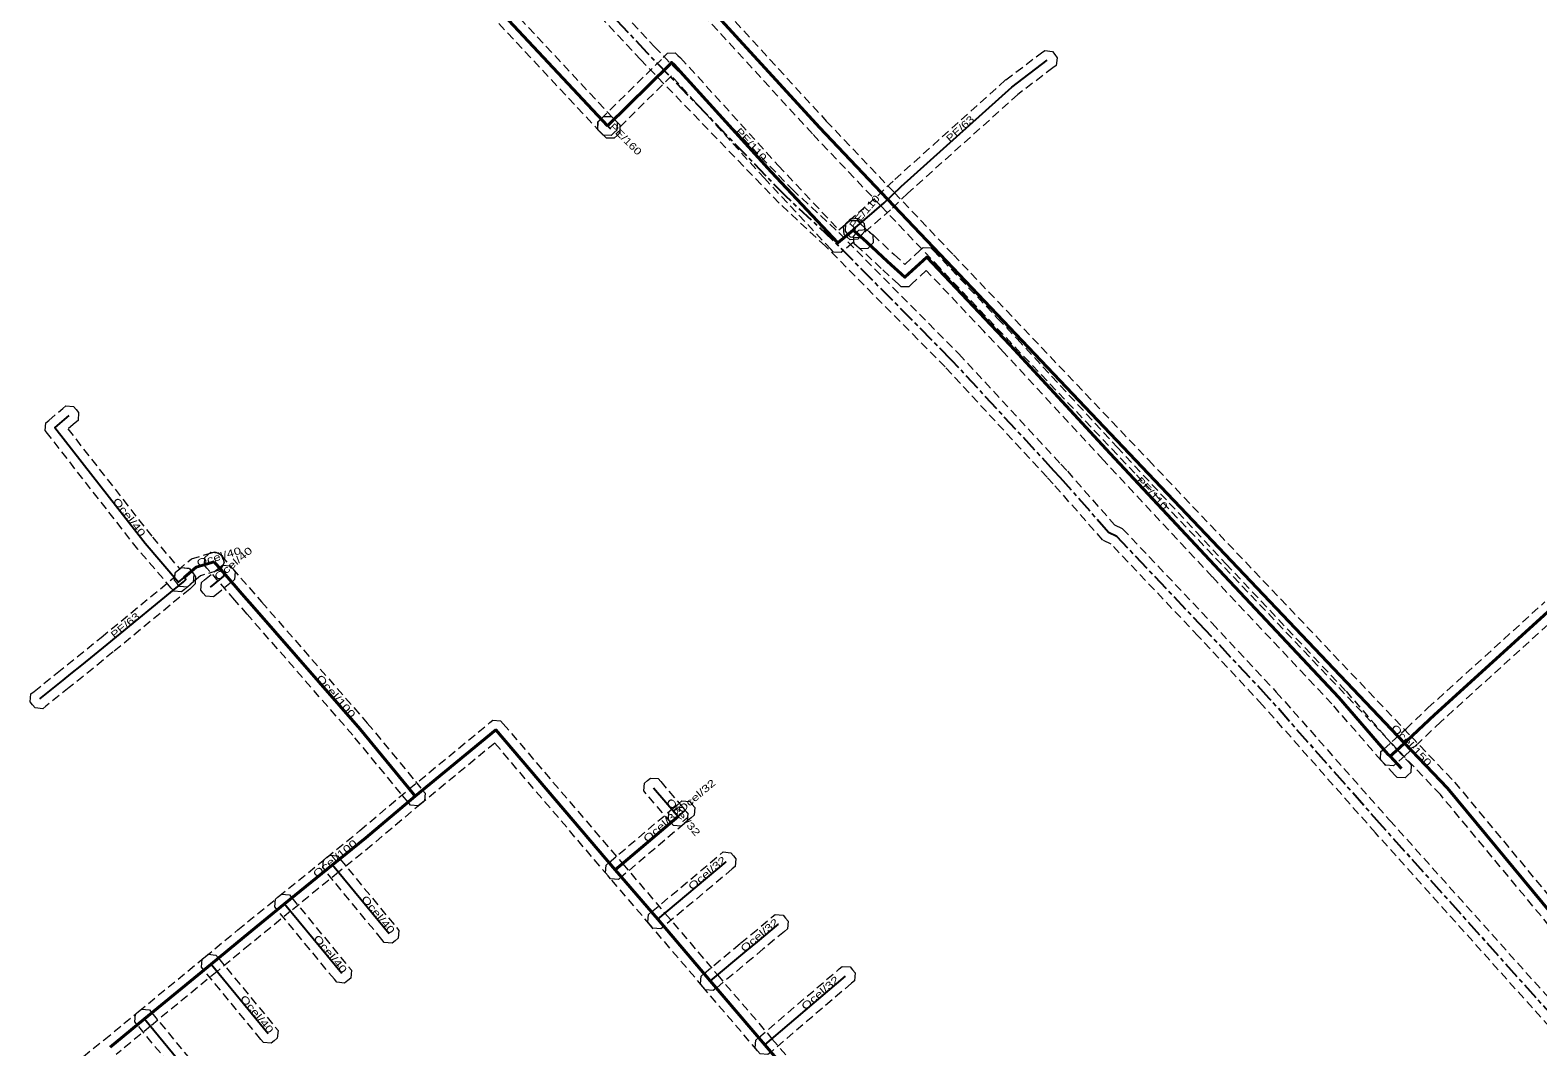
# Model space of a CAD drawing. Extents: x -588392 to -586332, y -1208963 to -1206334.
# Drawn here: x -588286.3 to -588126.9, y -1206548.1 to -1206440.6 of the extents above; entities that cross this region are included whole.
import ezdxf

# ---------------------------------------------------------------- set-up
doc = ezdxf.new("R2010")
doc.units = 0
doc.header["$LTSCALE"] = 0.3
doc.linetypes.add('LONG_DASH_SHORT_DASH', pattern=[9.9, 6, -1.2, 1.5, -1.2])
doc.linetypes.add('MEDIUM_DASHED', pattern=[4.5, 3, -1.5])
for name, color, linetype, lineweight in [('1', 7, 'MEDIUM_DASHED', 13), ('14', 7, 'Continuous', 25), ('24', 7, 'Continuous', 25), ('55', 7, 'LONG_DASH_SHORT_DASH', 25), ('7', 7, 'MEDIUM_DASHED', 13)]:
    doc.layers.add(name, color=color, linetype=linetype, lineweight=lineweight)
doc.layers.add('20', color=7, linetype='Continuous')
doc.layers.add('30', color=7, linetype='Continuous')

msp = doc.modelspace()

# ---------------------------------------------------------------- linework, layer by layer
at = {"layer": '1'}
for points in [[(-588105.041, -1206560.272), (-588137.218, -1206521.444), (-588141.774, -1206516.649), (-588169.516, -1206487.445), (-588190.167, -1206465.706), (-588196.423, -1206459.121), (-588203.622, -1206451.542), (-588247.155, -1206403.949), (-588247.425, -1206403.435), (-588247.618, -1206403.068), (-588247.372, -1206402.277), (-588247.005, -1206402.085), (-588246.638, -1206401.892), (-588245.847, -1206402.138), (-588245.655, -1206402.505), (-588245.505, -1206402.791), (-588202.158, -1206450.178), (-588194.973, -1206457.743), (-588188.717, -1206464.328), (-588168.066, -1206486.067), (-588140.324, -1206515.271), (-588135.722, -1206520.116), (-588103.501, -1206558.996)], [(-588242.864, -1206430.433), (-588224.569, -1206450.007), (-588224.287, -1206450.31), (-588224.315, -1206451.138), (-588224.617, -1206451.421), (-588224.92, -1206451.703), (-588225.748, -1206451.675), (-588226.031, -1206451.373), (-588244.316, -1206431.807)], [(-588124.832, -1206502.544), (-588137.17, -1206513.743), (-588139.475, -1206515.929), (-588140.957, -1206517.31), (-588141.866, -1206518.117), (-588142.175, -1206518.392), (-588143.002, -1206518.344), (-588143.277, -1206518.034), (-588143.552, -1206517.725), (-588143.504, -1206516.898), (-588143.194, -1206516.623), (-588142.303, -1206515.83), (-588140.845, -1206514.471), (-588138.53, -1206512.277), (-588126.168, -1206501.056)], [(-588282.82, -1206550.873), (-588278.513, -1206547.385), (-588274.885, -1206544.398), (-588267.845, -1206538.608), (-588264.394, -1206535.767), (-588260.072, -1206532.235), (-588254.991, -1206528.105), (-588251.478, -1206525.24), (-588246.26, -1206520.841), (-588237.725, -1206513.827), (-588237.409, -1206513.568), (-588236.594, -1206513.64), (-588236.329, -1206513.951), (-588223.71, -1206528.741), (-588219.229, -1206533.981), (-588213.679, -1206540.501), (-588207.9, -1206547.27), (-588200.519, -1206555.901)], [(-588209.42, -1206548.57), (-588215.201, -1206541.799), (-588220.751, -1206535.279), (-588225.23, -1206530.039), (-588237.214, -1206515.996), (-588244.98, -1206522.379), (-588250.202, -1206526.78), (-588253.729, -1206529.655), (-588258.808, -1206533.785), (-588263.126, -1206537.313), (-588266.575, -1206540.152), (-588273.615, -1206545.942), (-588277.247, -1206548.935)]]:
    msp.add_lwpolyline(points, dxfattribs=at)
for points in [[(-588208.705, -1206456.238), (-588218.522, -1206445.4), (-588224.597, -1206451.401), (-588224.892, -1206451.692), (-588225.72, -1206451.688), (-588226.011, -1206451.393), (-588226.302, -1206451.098), (-588226.298, -1206450.27), (-588226.003, -1206449.979), (-588219.415, -1206443.471), (-588219.217, -1206443.273), (-588218.938, -1206442.994), (-588218.149, -1206442.967), (-588217.851, -1206443.227), (-588217.568, -1206443.476), (-588207.235, -1206454.882), (-588200.846, -1206461.697), (-588199.941, -1206460.942), (-588199.653, -1206460.702), (-588198.903, -1206460.718), (-588198.626, -1206460.971), (-588197.559, -1206461.945), (-588197.253, -1206462.225), (-588197.215, -1206463.052), (-588197.494, -1206463.358), (-588197.774, -1206463.664), (-588198.601, -1206463.702), (-588198.907, -1206463.423), (-588199.33, -1206463.037), (-588200.289, -1206463.838), (-588200.594, -1206464.093), (-588201.388, -1206464.044), (-588201.66, -1206463.754)], [(-588200.078, -1206461.005), (-588199.765, -1206460.734), (-588196.714, -1206458.091), (-588194.911, -1206456.357), (-588183.177, -1206445.818), (-588179.394, -1206442.953), (-588179.064, -1206442.703), (-588178.243, -1206442.816), (-588177.993, -1206443.146), (-588177.743, -1206443.476), (-588177.856, -1206444.297), (-588178.186, -1206444.547), (-588181.903, -1206447.362), (-588193.549, -1206457.823), (-588195.366, -1206459.569), (-588198.455, -1206462.246), (-588198.768, -1206462.517), (-588199.595, -1206462.458), (-588199.866, -1206462.145), (-588200.137, -1206461.832)], [(-588224.886, -1206449.69), (-588224.593, -1206449.983), (-588224.283, -1206450.293), (-588223.99, -1206450.586), (-588223.99, -1206451.414), (-588224.283, -1206451.707), (-588224.576, -1206452), (-588225.404, -1206452), (-588225.697, -1206451.707), (-588226.007, -1206451.397), (-588226.3, -1206451.104), (-588226.3, -1206450.276), (-588226.007, -1206449.983), (-588225.714, -1206449.69)], [(-588198.083, -1206461.83), (-588198.353, -1206462.144), (-588198.543, -1206462.364), (-588198.814, -1206462.677), (-588199.64, -1206462.737), (-588199.954, -1206462.467), (-588200.267, -1206462.196), (-588200.327, -1206461.37), (-588200.057, -1206461.056), (-588199.867, -1206460.836), (-588199.596, -1206460.523), (-588198.77, -1206460.463), (-588198.456, -1206460.733), (-588198.143, -1206461.004)], [(-588197.908, -1206461.652), (-588197.59, -1206461.918), (-588197.217, -1206462.231), (-588194.992, -1206464.305), (-588193.847, -1206465.35), (-588192.221, -1206463.838), (-588191.919, -1206463.557), (-588191.096, -1206463.584), (-588190.813, -1206463.883), (-588184.044, -1206471.053), (-588181.99, -1206473.216), (-588171.407, -1206484.67), (-588159.89, -1206497.026), (-588147.198, -1206510.509), (-588142.035, -1206516.46), (-588141.816, -1206516.669), (-588140.595, -1206517.992), (-588140.314, -1206518.296), (-588140.348, -1206519.124), (-588140.652, -1206519.405), (-588140.956, -1206519.686), (-588141.784, -1206519.652), (-588142.065, -1206519.348), (-588143.244, -1206518.071), (-588143.485, -1206517.84), (-588148.682, -1206511.851), (-588161.35, -1206498.394), (-588172.873, -1206486.03), (-588183.45, -1206474.584), (-588185.496, -1206472.427), (-588191.586, -1206465.978), (-588193.159, -1206467.442), (-588193.445, -1206467.708), (-588194.225, -1206467.712), (-588194.514, -1206467.449), (-588196.348, -1206465.775), (-588198.543, -1206463.729), (-588198.876, -1206463.45), (-588199.193, -1206463.184), (-588199.265, -1206462.359), (-588198.999, -1206462.041), (-588198.733, -1206461.724)], [(-588273.415, -1206494.207), (-588270.548, -1206497.562), (-588270.392, -1206497.43), (-588269.566, -1206497.496), (-588269.298, -1206497.812), (-588269.03, -1206498.128), (-588269.096, -1206498.954), (-588269.412, -1206499.222), (-588270.012, -1206499.732), (-588270.327, -1206500), (-588271.151, -1206499.934), (-588271.42, -1206499.62), (-588274.965, -1206495.473), (-588284.528, -1206483.225), (-588284.776, -1206482.908), (-588284.693, -1206482.106), (-588284.386, -1206481.846), (-588282.896, -1206480.586), (-588282.58, -1206480.319), (-588281.754, -1206480.388), (-588281.486, -1206480.704), (-588281.219, -1206481.02), (-588281.288, -1206481.846), (-588281.604, -1206482.114), (-588282.36, -1206482.753)], [(-588271.025, -1206497.97), (-588270.71, -1206497.7), (-588269.299, -1206496.492), (-588267.186, -1206495.862), (-588266.789, -1206495.744), (-588266.06, -1206496.137), (-588265.942, -1206496.534), (-588265.824, -1206496.931), (-588266.217, -1206497.66), (-588266.614, -1206497.778), (-588268.321, -1206498.288), (-588269.41, -1206499.22), (-588269.724, -1206499.489), (-588270.55, -1206499.425), (-588270.82, -1206499.11), (-588271.089, -1206498.796)], [(-588266.421, -1206495.85), (-588266.148, -1206496.161), (-588264.947, -1206497.532), (-588263.196, -1206499.543), (-588261.877, -1206501.052), (-588250.697, -1206513.873), (-588245.598, -1206520.064), (-588244.848, -1206520.974), (-588244.585, -1206521.294), (-588244.664, -1206522.119), (-588244.984, -1206522.382), (-588245.304, -1206522.645), (-588246.129, -1206522.566), (-588246.392, -1206522.246), (-588247.142, -1206521.336), (-588252.223, -1206515.167), (-588263.383, -1206502.368), (-588264.704, -1206500.857), (-588266.453, -1206498.848), (-588267.652, -1206497.479), (-588267.925, -1206497.168), (-588267.87, -1206496.341), (-588267.559, -1206496.068), (-588267.248, -1206495.795)], [(-588278.822, -1206504.805), (-588271.064, -1206498.416), (-588270.991, -1206497.909), (-588270.66, -1206497.66), (-588270.329, -1206497.411), (-588269.509, -1206497.529), (-588269.26, -1206497.86), (-588269.08, -1206498.1), (-588268.853, -1206498.403), (-588268.914, -1206499.158), (-588269.187, -1206499.421), (-588269.475, -1206499.697), (-588277.558, -1206506.355), (-588282.233, -1206510.129), (-588284.683, -1206512.099), (-588285.006, -1206512.359), (-588285.83, -1206512.27), (-588286.089, -1206511.947), (-588286.349, -1206511.624), (-588286.26, -1206510.8), (-588285.937, -1206510.541), (-588283.487, -1206508.571)], [(-588268.229, -1206498.998), (-588267.911, -1206498.732), (-588266.341, -1206497.422), (-588266.023, -1206497.157), (-588265.198, -1206497.231), (-588264.932, -1206497.549), (-588264.667, -1206497.867), (-588264.741, -1206498.692), (-588265.059, -1206498.958), (-588266.629, -1206500.268), (-588266.947, -1206500.533), (-588267.772, -1206500.459), (-588268.038, -1206500.141), (-588268.303, -1206499.823)], [(-588219.939, -1206519.755), (-588219.67, -1206520.07), (-588217.07, -1206523.11), (-588216.801, -1206523.425), (-588216.865, -1206524.251), (-588217.18, -1206524.52), (-588217.495, -1206524.789), (-588218.321, -1206524.725), (-588218.59, -1206524.41), (-588221.19, -1206521.37), (-588221.459, -1206521.055), (-588221.395, -1206520.229), (-588221.08, -1206519.96), (-588220.765, -1206519.691)], [(-588225.433, -1206528.895), (-588225.117, -1206528.627), (-588218.477, -1206522.997), (-588218.161, -1206522.729), (-588217.335, -1206522.797), (-588217.067, -1206523.113), (-588216.799, -1206523.429), (-588216.867, -1206524.255), (-588217.183, -1206524.523), (-588223.823, -1206530.153), (-588224.139, -1206530.421), (-588224.965, -1206530.353), (-588225.233, -1206530.037), (-588225.501, -1206529.721)], [(-588218.793, -1206523.266), (-588218.477, -1206522.998), (-588217.747, -1206522.378), (-588217.431, -1206522.11), (-588216.606, -1206522.177), (-588216.338, -1206522.493), (-588216.07, -1206522.809), (-588216.137, -1206523.634), (-588216.453, -1206523.902), (-588217.183, -1206524.522), (-588217.499, -1206524.79), (-588218.324, -1206524.723), (-588218.592, -1206524.407), (-588218.86, -1206524.091)], [(-588253.851, -1206527.925), (-588253.588, -1206528.245), (-588247.615, -1206535.503), (-588247.352, -1206535.823), (-588247.432, -1206536.647), (-588247.752, -1206536.91), (-588248.072, -1206537.173), (-588248.896, -1206537.093), (-588249.159, -1206536.773), (-588255.132, -1206529.515), (-588255.395, -1206529.195), (-588255.315, -1206528.371), (-588254.995, -1206528.108), (-588254.675, -1206527.845)], [(-588220.95, -1206534.13), (-588220.633, -1206533.864), (-588213.383, -1206527.784), (-588213.065, -1206527.518), (-588212.24, -1206527.59), (-588211.974, -1206527.907), (-588211.708, -1206528.225), (-588211.78, -1206529.05), (-588212.097, -1206529.316), (-588219.347, -1206535.396), (-588219.665, -1206535.662), (-588220.49, -1206535.59), (-588220.756, -1206535.273), (-588221.022, -1206534.955)], [(-588258.931, -1206532.055), (-588258.668, -1206532.375), (-588252.634, -1206539.713), (-588252.371, -1206540.033), (-588252.451, -1206540.857), (-588252.771, -1206541.12), (-588253.091, -1206541.383), (-588253.915, -1206541.303), (-588254.178, -1206540.983), (-588260.212, -1206533.645), (-588260.475, -1206533.325), (-588260.395, -1206532.501), (-588260.075, -1206532.238), (-588259.755, -1206531.975)], [(-588206.273, -1206535.665), (-588206.592, -1206535.93), (-588208.821, -1206537.779), (-588209.941, -1206538.709), (-588213.801, -1206541.919), (-588214.119, -1206542.184), (-588214.944, -1206542.108), (-588215.209, -1206541.789), (-588215.474, -1206541.471), (-588215.398, -1206540.646), (-588215.079, -1206540.381), (-588211.219, -1206537.171), (-588210.099, -1206536.241), (-588207.868, -1206534.39), (-588207.549, -1206534.126), (-588206.725, -1206534.203), (-588206.46, -1206534.522), (-588206.196, -1206534.841)], [(-588266.701, -1206538.425), (-588266.438, -1206538.745), (-588260.401, -1206546.08), (-588260.138, -1206546.4), (-588260.218, -1206547.224), (-588260.538, -1206547.487), (-588260.858, -1206547.75), (-588261.682, -1206547.67), (-588261.945, -1206547.35), (-588267.982, -1206540.015), (-588268.245, -1206539.695), (-588268.165, -1206538.871), (-588267.845, -1206538.608), (-588267.525, -1206538.345)], [(-588209.624, -1206547.428), (-588209.309, -1206547.159), (-588200.789, -1206539.889), (-588200.474, -1206539.62), (-588199.648, -1206539.686), (-588199.379, -1206540.001), (-588199.11, -1206540.316), (-588199.176, -1206541.142), (-588199.491, -1206541.411), (-588208.011, -1206548.681), (-588208.326, -1206548.95), (-588209.152, -1206548.884), (-588209.421, -1206548.569), (-588209.69, -1206548.254)], [(-588273.741, -1206544.214), (-588273.478, -1206544.534), (-588267.598, -1206551.674), (-588267.335, -1206551.994), (-588267.414, -1206552.819), (-588267.734, -1206553.082), (-588268.054, -1206553.345), (-588268.879, -1206553.266), (-588269.142, -1206552.946), (-588275.022, -1206545.806), (-588275.285, -1206545.486), (-588275.206, -1206544.661), (-588274.886, -1206544.398), (-588274.566, -1206544.135)]]:
    msp.add_lwpolyline(points, close=True, dxfattribs=at)
at = {"layer": '14'}
for p, q in [((-588267.27, -1206499.5), (-588265.7, -1206498.19)), ((-588254.36, -1206528.88), (-588248.387, -1206536.138)), ((-588219.99, -1206534.63), (-588212.74, -1206528.55)), ((-588259.44, -1206533.01), (-588253.406, -1206540.348)), ((-588267.21, -1206539.38), (-588261.173, -1206546.715)), ((-588208.66, -1206547.92), (-588200.14, -1206540.65)), ((-588274.25, -1206545.17), (-588268.37, -1206552.31))]:
    msp.add_line(p, q, dxfattribs=at)
at = {"layer": '14', "lineweight": 40}
msp.add_line((-588224.47, -1206529.39), (-588217.83, -1206523.76), dxfattribs=at)
at = {"layer": '14'}
for points in [[(-588282.25, -1206481.35), (-588283.74, -1206482.61), (-588274.19, -1206494.84), (-588270.66, -1206498.97), (-588270.06, -1206498.46)], [(-588285.31, -1206511.32), (-588282.86, -1206509.35), (-588282.03, -1206508.68), (-588280.88, -1206507.75), (-588278.19, -1206505.58), (-588270.14, -1206498.95), (-588269.88, -1206498.7), (-588270.06, -1206498.46)], [(-588220.43, -1206520.72), (-588217.83, -1206523.76), (-588217.1, -1206523.14)], [(-588207.23, -1206535.16), (-588209.46, -1206537.01), (-588210.58, -1206537.94), (-588214.44, -1206541.15)]]:
    msp.add_lwpolyline(points, dxfattribs=at)
at = {"layer": '14', "lineweight": 40}
for points in [[(-588270.06, -1206498.46), (-588268.81, -1206497.39), (-588266.9, -1206496.82)], [(-588266.9, -1206496.82), (-588265.7, -1206498.19), (-588263.95, -1206500.2), (-588262.63, -1206501.71), (-588251.46, -1206514.52), (-588246.37, -1206520.7), (-588245.62, -1206521.61)], [(-588201.28, -1206556.55), (-588208.66, -1206547.92), (-588214.44, -1206541.15), (-588219.99, -1206534.63), (-588224.47, -1206529.39), (-588237.09, -1206514.6), (-588245.62, -1206521.61), (-588250.84, -1206526.01), (-588254.36, -1206528.88), (-588259.44, -1206533.01), (-588263.76, -1206536.54), (-588267.21, -1206539.38), (-588274.25, -1206545.17), (-588277.88, -1206548.16)]]:
    msp.add_lwpolyline(points, dxfattribs=at)
at = {"layer": '24'}
msp.add_line((-588225.3, -1206450.69), (-588224.99, -1206451), dxfattribs=at)
at = {"layer": '24', "lineweight": 40}
msp.add_line((-588199.11, -1206461.49), (-588199.3, -1206461.71), dxfattribs=at)
for points in [[(-588246.54, -1206402.97), (-588246.33, -1206403.37), (-588202.89, -1206450.86), (-588195.698, -1206458.432), (-588189.442, -1206465.017), (-588168.791, -1206486.756), (-588141.049, -1206515.96), (-588136.47, -1206520.78), (-588104.271, -1206559.634), (-588072.7, -1206597.73), (-588057.802, -1206615.664), (-588044.559, -1206631.23)], [(-588267.11, -1206408.46), (-588266.17, -1206409.35), (-588264.86, -1206408.91), (-588243.59, -1206431.12), (-588225.3, -1206450.69)], [(-588198.233, -1206462.684), (-588199.3, -1206461.71), (-588200.93, -1206463.07), (-588207.97, -1206455.56), (-588218.27, -1206444.19), (-588218.51, -1206443.98), (-588218.71, -1206444.18), (-588225.3, -1206450.69)], [(-588198.233, -1206462.684), (-588197.88, -1206462.98), (-588195.67, -1206465.04), (-588193.84, -1206466.71), (-588191.54, -1206464.57), (-588184.77, -1206471.74), (-588182.72, -1206473.9), (-588172.14, -1206485.35), (-588160.62, -1206497.71), (-588147.94, -1206511.18), (-588142.76, -1206517.15), (-588142.53, -1206517.37), (-588141.33, -1206518.67)], [(-588142.53, -1206517.37), (-588141.63, -1206516.57), (-588140.16, -1206515.2), (-588137.85, -1206513.01), (-588125.5, -1206501.8), (-588114.65, -1206492.16), (-588111.33, -1206489.04), (-588095.14, -1206474.33), (-588092.692, -1206472.128), (-588080.969, -1206461.585)]]:
    msp.add_lwpolyline(points, dxfattribs=at)
at = {"layer": '24'}
msp.add_lwpolyline([(-588199.11, -1206461.49), (-588196.04, -1206458.83), (-588194.23, -1206457.09), (-588182.54, -1206446.59), (-588178.79, -1206443.75)], dxfattribs=at)
at = {"layer": '55'}
msp.add_lwpolyline([(-588123.14, -1206547.36), (-588143.33, -1206524.83), (-588155.31, -1206511.27), (-588162.09, -1206504), (-588171.42, -1206494.14), (-588172.31, -1206493.7), (-588177.41, -1206487.9), (-588178.08, -1206487.18), (-588188.87, -1206475.5), (-588201.54, -1206462.7), (-588206.44, -1206458.14), (-588221.05, -1206443.01), (-588235.4, -1206427.64), (-588240.56, -1206421.71), (-588249.95, -1206411.8), (-588257.85, -1206403.33), (-588261.263, -1206399.627), (-588260.42, -1206398.88), (-588260.56, -1206398.73), (-588260.763, -1206398.901), (-588261.398, -1206398.196), (-588261.08, -1206397.93)], dxfattribs=at)
at = {"layer": '7'}
for points in [[(-588123.889, -1206548.022), (-588144.077, -1206525.495), (-588156.051, -1206511.942), (-588162.819, -1206504.685), (-588172.023, -1206494.957), (-588172.93, -1206494.509), (-588178.152, -1206488.571), (-588178.813, -1206487.86), (-588189.593, -1206476.191), (-588202.236, -1206463.418), (-588207.141, -1206458.854), (-588221.775, -1206443.699), (-588236.143, -1206428.31), (-588241.3, -1206422.382), (-588250.679, -1206412.485), (-588258.583, -1206404.01), (-588261.998, -1206400.305), (-588262.283, -1206399.996), (-588262.262, -1206399.577), (-588262.241, -1206399.157), (-588262.039, -1206398.979), (-588262.141, -1206398.865), (-588262.425, -1206398.549), (-588262.396, -1206398.126)], [(-588234.657, -1206426.97), (-588220.325, -1206442.321), (-588205.739, -1206457.426), (-588200.844, -1206461.982), (-588188.147, -1206474.809), (-588177.347, -1206486.5), (-588176.668, -1206487.229), (-588171.69, -1206492.891), (-588170.817, -1206493.323), (-588161.361, -1206503.315), (-588154.569, -1206510.598), (-588142.583, -1206524.165), (-588122.391, -1206546.698)]]:
    msp.add_lwpolyline(points, dxfattribs=at)

# ---------------------------------------------------------------- texts
at = {"layer": '20'}
for s, rotation, width, p in [('Ocel/40', 307.985, 1.4, (-588277.651, -1206490.407)), ('Ocel/40', 16.617, 1.4, (-588268.596, -1206497.326)), ('Ocel/40', 39.841, 1.4, (-588266.485, -1206498.845)), ('PE/63', 39.475, 1.3, (-588277.44, -1206504.962)), ('Ocel/100', 311.088, 1.4, (-588256.127, -1206509.168)), ('Ocel/32', 40.342, 1.4, (-588217.465, -1206523.45)), ('Ocel/32', 310.539, 1.4, (-588219.13, -1206522.24)), ('Ocel/32', 40.294, 1.4, (-588221.112, -1206526.542)), ('Ocel/100', 39.111, 1.4, (-588256.06, -1206530.262)), ('Ocel/32', 39.984, 1.4, (-588216.365, -1206531.59)), ('Ocel/40', 309.453, 1.4, (-588251.373, -1206532.509)), ('Ocel/32', 39.747, 1.4, (-588210.837, -1206538.153)), ('Ocel/40', 309.43, 1.4, (-588256.423, -1206536.679)), ('Ocel/32', 40.474, 1.4, (-588204.4, -1206544.285)), ('Ocel/40', 309.456, 1.4, (-588264.191, -1206543.047))]:
    msp.add_text(s, height=0.75, rotation=rotation, dxfattribs=dict(at, width=width)).set_placement(p)
at = {"layer": '30'}
for s, rotation, width, p in [('PE/63', 41.93, 1.3, (-588189.08, -1206452.464)), ('PE/160', 315, 1.3, (-588225.145, -1206450.845)), ('PE/110', 312.173, 1.3, (-588211.812, -1206451.319)), ('PE/110', 49.185, 1.3, (-588199.238, -1206461.638)), ('PE/110', 312.985, 1.3, (-588169.427, -1206488.26)), ('Ocel/150', 313.529, 1.4, (-588142.483, -1206514.451))]:
    msp.add_text(s, height=0.75, rotation=rotation, dxfattribs=dict(at, width=width)).set_placement(p)

doc.saveas('drawing.dxf')
